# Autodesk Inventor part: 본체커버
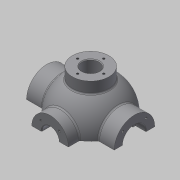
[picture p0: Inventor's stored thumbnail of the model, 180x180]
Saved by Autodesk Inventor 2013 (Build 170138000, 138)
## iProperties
Created: 2015-12
Part Number: 본체커버
Material: 일반
Document SubType Name: Modeling
Designer: mduedu
Density: 2.71 g/cm^3
Mass: 574.351 g
Surface Area: 450.515 cm^2
Volume: 211.938 cm^3
Author: mduedu
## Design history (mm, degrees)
sketch "스케치1"
  geometry: L1 (-53, 0)-(53, 0); A1 r 53 centre (0, 0) between (53, 0) and (-53, 0); 2 further points
  constraints: 2 coincident, 2 end point, 2 point on circle, 1 centre point, 1 horizontal, 1 midpoint
  dimensions: "d0" = 53 radius of A1
revolve "회전1" sketch "스케치1" stored, may be unused: angle "d2" = 90 deg
feature "쉘1" dims "d11" = 10
node "작업 평면1"
sketch "스케치2"
  geometry: C1 r 31 at (0, 0); 1 further point
  constraints: 1 centre point, 1 coincident
  dimensions: "d4" = 62 diameter of C1
extrude "돌출1" join sketch "스케치2" stored distance "d5" = 10; taper "d6" = 0 deg
node "작업 평면2"
sketch "스케치3"
  geometry: C1 r 28 at (0, 0); 1 further point
  constraints: 1 centre point, 1 coincident
  dimensions: "d8" = 56 diameter of C1
extrude "돌출2" join sketch "스케치3" stored distance "d9" = 10; taper "d10" = 0 deg
hole "구멍1" diameter "d14" = 35; stored, may be unused: countersink angle "d18" = 90 deg, drill point angle "d20" = 0 deg; dims "d12" = 10, "d13" = 10, "d15" = 6, "d16" = 4, "d17" = 2, "d19" = 16
hole "구멍2" diameter "d23" = 27; stored, may be unused: countersink angle "d27" = 90 deg, drill point angle "d29" = 0 deg; dims "d21" = 10, "d22" = 10, "d24" = 6, "d25" = 4, "d26" = 2, "d28" = 16
fillet "모깎기1" dims "d30" = 0.3
hole "구멍3" diameter "d33" = 26; stored, may be unused: countersink angle "d37" = 90 deg, drill point angle "d39" = 0 deg; dims "d31" = 10, "d32" = 10, "d34" = 6, "d35" = 4, "d36" = 2, "d38" = 16
chamfer "모따기1" distance "d40" = 1; stored, may be unused: second distance "d41" = 2, angle "d42" = 45 deg
sketch "스케치4"
  geometry: L1 (0, 0)-(0, -25); L2 (0, 0)-(-17.678, -17.678); A1 r 25 centre (0, 0) between (-17.678, -17.678) and (0, -25); 1 further point
  constraints: 4 end point, 2 point on circle, 1 centre point, 1 coincident, 1 vertical
  dimensions: "d43" = 50 diameter of A1; "d47" = 45 deg angle of L1 L2
hole "구멍4" sketch "스케치4" at (-17.678, -17.678) diameter "d49" = 3.242; stored, may be unused: countersink angle "d53" = 90 deg, drill point angle "d55" = 118 deg; dims "d50" = 11, "d51" = 4, "d52" = 2, "d54" = 13
sketch "스케치5"
  geometry: L1 (0, 0)-(0, -20); L2 (0, 0)-(-14.142, -14.142); A1 r 20 centre (0, 0) between (0, -20) and (-14.142, -14.142); 2 further points
  constraints: 4 end point, 2 coincident, 2 point on circle, 1 centre point, 1 vertical
  dimensions: "d59" = 40 diameter of A1; "d65" = 45 deg angle of L1 L2
hole "구멍5" sketch "스케치5" at (-14.142, -14.142) diameter "d67" = 3.242; stored, may be unused: countersink angle "d71" = 90 deg, drill point angle "d73" = 118 deg; dims "d68" = 8, "d69" = 4, "d70" = 2, "d72" = 10
node "작업 평면3"
sketch "스케치6"
  geometry: C1 r 65 at (0, 0); 1 further point
  constraints: 1 centre point, 1 coincident
  dimensions: "d78" = 130 diameter of C1
extrude "돌출3" join sketch "스케치6" distance "d80" = 10; taper "d81" = 0 deg
sketch "스케치7"
  geometry: C1 r 20 at (0, 0); 1 further point
  constraints: 1 centre point, 1 coincident
  dimensions: "d82" = 40 diameter of C1
extrude "돌출4" join sketch "스케치7" stored distance "d84" = 10; taper "d85" = 0 deg
sketch "스케치8"
  geometry: 2 further points
  constraints: 1 coincident
hole "구멍6" sketch "스케치8" at (0, 0) diameter "d86" = 20; stored, may be unused: countersink angle "d90" = 90 deg, drill point angle "d92" = 118 deg; dims "d87" = 7, "d88" = 40, "d89" = 5, "d91" = 10
fillet "모깎기2" dims "d93" = 0.3
sketch "스케치9"
  geometry: L1 (65, -75)-(-65, -75) reference; L2 (-45, -75)-(-38.245, -36.692); A1 r 53 centre (0, 0) between (42.988, 31) and (42.988, -31) reference; 1 further point
  constraints: 2 end point, 1 point on circle, 1 point on line
  dimensions: "d94" = 45 horizontal distance of L2.start point (0, 0); "d95" = 80 deg angle of L2 L1
feature "리브1" sketch "스케치9" dims "d96" = 1, "d97" = 8, "d98" = 0, "d99" = 0, "d100" = 1, "d101" = 1
sketch "스케치10"
  geometry: L1 (0, 0)-(0, -55); L2 (0, 0)-(-38.891, -38.891); A1 r 55 centre (0, 0) between (0, -55) and (-38.891, -38.891); 2 further points
  constraints: 4 end point, 2 coincident, 2 point on circle, 1 centre point, 1 vertical
  dimensions: "d105" = 110 diameter of A1; "d107" = 45 deg angle of L1 L2
hole "구멍7" sketch "스케치10" at (-38.891, -38.891) diameter "d109" = 10; stored, may be unused: countersink angle "d113" = 90 deg, drill point angle "d115" = 118 deg; dims "d110" = 7, "d111" = 40, "d112" = 5, "d114" = 10
fillet "모깎기3" dims "d120" = 3
fillet "모깎기4" dims "d121" = 3, "d122" = 3
fillet "모깎기5" dims "d123" = 3
fillet "모깎기6" dims "d124" = 3
sketch "스케치11"
  geometry: C1 r 5 at (-38.891, 38.891) reference; C2 r 5 at (38.891, 38.891) reference; C3 r 5 at (38.891, -38.891) reference; C4 r 5 at (-38.891, -38.891) reference; C5 r 20 at (0, 0) reference; C6 r 65 at (0, 0) reference; 1 further point
  constraints: 3 other
feature "엠보싱1" sketch "스케치11" dims "d125" = 0.5, "d126" = 0
sketch "스케치12"
  geometry: L1 (0, 100)-(0, -100); L2 (0, 100)-(-150, 100); L3 (-150, 100)-(-150, -100); L4 (-150, -100)-(0, -100); 2 further points
  constraints: 8 end point, 3 perpendicular, 1 coincident, 1 midpoint, 1 vertical
  dimensions: "d127" = 200 distance of L2.end L3.end; "d129" = 150 distance of L3.end L1.end
extrude "돌출5" cut sketch "스케치12" stored distance "d130" = 10; taper "d131" = 0 deg
sketch "스케치13"
  geometry: C1 r 7 at (0, -53); A1 r 53 centre (0, 0) between (-42.113, -32.179) and (42.113, -32.179) reference; 1 further point
  constraints: 1 centre point, 1 point on circle
  dimensions: "d132" = 14 diameter of C1
extrude "돌출6" join sketch "스케치13" distance "d133" = 5; taper "d134" = 0 deg
sketch "스케치14"
  geometry: C1 r 7 at (0, 0) reference; 1 further point
extrude "돌출7" cut sketch "스케치14" stored distance "d135" = 5; taper "d136" = 0 deg
sketch "스케치15"
  geometry: C1 r 2.25 at (0, 53); A1 r 7 centre (0, 53) between (6.965, 52.302) and (-6.965, 52.302) reference; 1 further point
  constraints: 1 centre point, 1 coincident
  dimensions: "d139" = 4.5 diameter of C1
extrude "돌출8" cut sketch "스케치15" stored distance "d141" = 5; taper "d142" = 0 deg
fillet "모깎기7" dims "d143" = 3
fillet "모깎기8" dims "d144" = 1
fillet "모깎기9" dims "d145" = 1
fillet "모깎기10" dims "d146" = 1
node "작업 평면4"
sketch "스케치16"
  geometry: C1 r 28 at (0, 0); 1 further point
  constraints: 1 centre point, 1 coincident
  dimensions: "d148" = 56 diameter of C1
extrude "돌출9" join sketch "스케치16" stored distance "d150" = 5; taper "d151" = 0 deg
hole "구멍8" diameter "d154" = 26; stored, may be unused: countersink angle "d158" = 90 deg, drill point angle "d160" = 118 deg; dims "d152" = 10, "d153" = 10, "d155" = 6, "d156" = 4, "d157" = 2, "d159" = 8
sketch "스케치17" dims "d161" = 40
  geometry: 3 further points
  constraints: 2 vertical alignment, 1 coincident, 2 other
hole "구멍9" sketch "스케치17" at (0, 20) diameter "d163" = 3.242; stored, may be unused: countersink angle "d167" = 90 deg, drill point angle "d169" = 118 deg; dims "d164" = 8, "d165" = 4, "d166" = 2, "d168" = 10
fillet "모깎기11" dims "d173" = 3
chamfer "모따기2" distance "d174" = 1; stored, may be unused: second distance "d175" = 2, angle "d176" = 45 deg
node "솔리드1"
mirror "대칭1"
mirror "대칭2"
pattern_circular "원형 패턴1" dims angle "d57" = 360 deg
mirror "대칭3"
pattern_circular "원형 패턴2" dims angle "d75" = 360 deg
pattern_circular "원형 패턴3" dims angle "d103" = 360 deg
pattern_circular "원형 패턴4" dims angle "d118" = 360 deg
pattern_circular "원형 패턴5" dims angle "d171" = 360 deg
node "투영된 루프1"
other parameters: "d3" = 67, "d7" = 62, "d77" = -85, "d147" = 62
